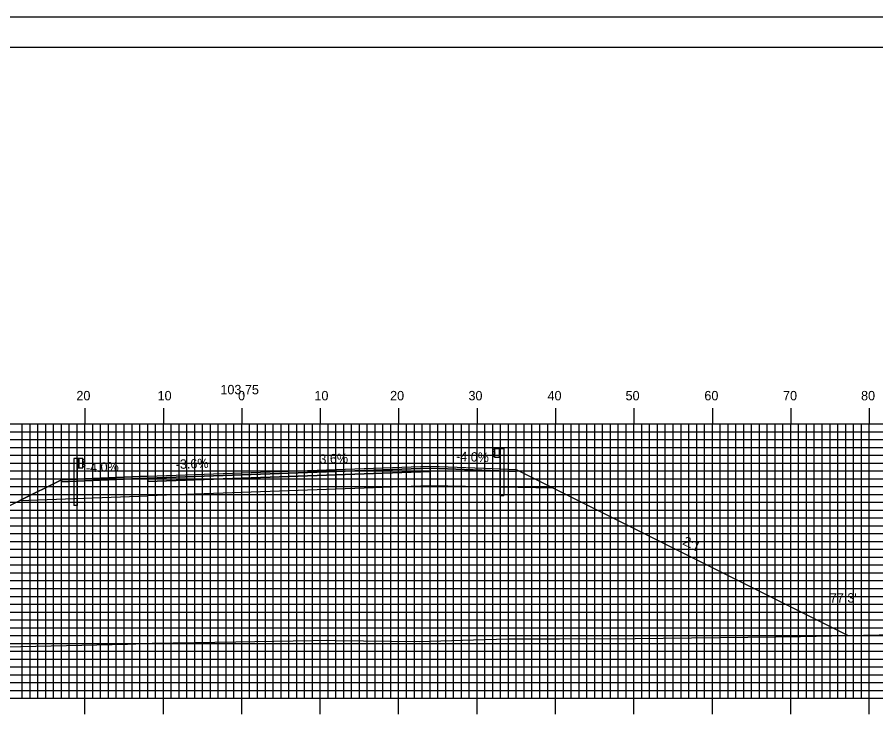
# Model space of a CAD drawing. Extents: x 1759430 to 1759773, y 442591 to 442811.
# Drawn here: x 1759567 to 1759676.5, y 442721.2 to 442810.5 of the extents above; entities that cross this region are included whole.
import ezdxf

# ---------------------------------------------------------------- set-up
doc = ezdxf.new("R2010")
doc.units = 0
for name, color, linetype in [('ANNOTATION', 7, 'Continuous'), ('BORDER', 7, 'Continuous'), ('D_Guardrail_Beam_Lt', 7, 'Continuous'), ('D_Guardrail_Beam_Rt', 7, 'Continuous'), ('D_Roadway_Centerline', 7, 'Continuous'), ('D_Roadway_Centerline_Text', 7, 'Continuous'), ('D_Roadway_Edge_Shoulder', 7, 'Continuous'), ('D_Roadway_Edge_TW', 7, 'Continuous'), ('D_Roadway_Pavement', 7, 'Continuous'), ('D_Roadway_SlopeLines', 7, 'Continuous'), ('D_Roadway_SubGrade', 7, 'Continuous'), ('D_Text_Standard', 7, 'Continuous'), ('H_V ANNOTATION', 7, 'Continuous'), ('MAJOR', 7, 'Continuous'), ('MINOR', 7, 'Continuous'), ('PLOT BOUNDARY', 7, 'Continuous'), ('S_Roadway_Centerline', 7, 'Continuous')]:
    doc.layers.add(name, color=color, linetype=linetype)

msp = doc.modelspace()

# ---------------------------------------------------------------- linework, layer by layer
at = {"layer": 'BORDER'}
msp.add_lwpolyline([(1759446.07, 442596.67), (1759766.07, 442596.67), (1759766.07, 442806.67), (1759446.07, 442806.67)], close=True, dxfattribs=at)
at = {"layer": 'D_Guardrail_Beam_Lt'}
for p, q in [((1759574.25, 442754.25), (1759574.25, 442748.25)), ((1759574.72, 442754.25), (1759574.25, 442754.25)), ((1759575.4, 442754.25), (1759574.72, 442754.25)), ((1759574.72, 442754.25), (1759574.72, 442753.08)), ((1759574.78, 442754.25), (1759574.78, 442753.08)), ((1759574.88, 442754.25), (1759574.88, 442753.08)), ((1759575.4, 442753.08), (1759575.4, 442754.25)), ((1759575.4, 442754.16), (1759575.48, 442754.15)), ((1759575.49, 442754.14), (1759575.64, 442754.04)), ((1759574.72, 442753.08), (1759575.4, 442753.08)), ((1759574.74, 442748.25), (1759574.74, 442753.08)), ((1759575.48, 442753.18), (1759575.4, 442753.16)), ((1759575.41, 442753.7), (1759575.41, 442753.63)), ((1759575.64, 442753.9), (1759575.44, 442753.76)), ((1759575.44, 442753.56), (1759575.64, 442753.43)), ((1759575.64, 442753.28), (1759575.49, 442753.18)), ((1759574.74, 442748.25), (1759574.25, 442748.25))]:
    msp.add_line(p, q, dxfattribs=at)
for centre, major_axis, start_param, end_param in [((1759575.47, 442754.11), (0.0417, 0), 0.959931, 1.376053), ((1759575.59, 442753.97), (0.0877, 0), 5.323254, 7.243116), ((1759575.49, 442753.7), (-0.0789, 0), 5.323254, 6.283185), ((1759575.49, 442753.63), (-0.0789, 0), 6.283185, 7.243116), ((1759575.47, 442753.22), (0.0417, 0), 4.907132, 5.323254), ((1759575.59, 442753.36), (0.0877, 0), 5.323254, 7.243116)]:
    msp.add_ellipse(centre, major_axis=major_axis, ratio=0.995501, start_param=start_param, end_param=end_param, dxfattribs=at)
at = {"layer": 'D_Guardrail_Beam_Rt'}
for p, q in [((1759627.86, 442755.44), (1759627.71, 442755.34)), ((1759627.71, 442755.19), (1759627.91, 442755.06)), ((1759627.95, 442755.46), (1759627.87, 442755.44)), ((1759627.95, 442755.54), (1759628.63, 442755.54)), ((1759627.95, 442754.38), (1759627.95, 442755.54)), ((1759628.47, 442755.54), (1759628.47, 442754.38)), ((1759628.57, 442755.54), (1759628.57, 442754.38)), ((1759628.63, 442755.54), (1759629.1, 442755.54)), ((1759628.63, 442755.54), (1759628.63, 442754.38)), ((1759629.1, 442755.54), (1759629.1, 442749.54)), ((1759627.91, 442754.86), (1759627.71, 442754.72)), ((1759627.71, 442754.58), (1759627.86, 442754.48)), ((1759627.87, 442754.47), (1759627.95, 442754.46)), ((1759627.94, 442754.99), (1759627.94, 442754.92)), ((1759628.63, 442754.38), (1759627.95, 442754.38)), ((1759628.61, 442749.54), (1759628.61, 442754.38)), ((1759628.61, 442749.54), (1759629.1, 442749.54))]:
    msp.add_line(p, q, dxfattribs=at)
for centre, major_axis, start_param, end_param in [((1759627.76, 442755.27), (-0.0877, 0), 5.323254, 7.243116), ((1759627.88, 442755.4), (-0.0417, 0), 4.907132, 5.323254), ((1759627.76, 442754.65), (-0.0877, 0), 5.323254, 7.243116), ((1759627.88, 442754.51), (-0.0417, 0), 0.959931, 1.376053), ((1759627.86, 442754.99), (0.0789, 0), 0, 0.959931), ((1759627.86, 442754.92), (0.0789, 0), 5.323254, 6.283185)]:
    msp.add_ellipse(centre, major_axis=major_axis, ratio=0.995501, start_param=start_param, end_param=end_param, dxfattribs=at)
at = {"layer": 'D_Roadway_Centerline'}
msp.add_lwpolyline([(1759529.64, 442730.03), (1759567.38, 442748.9), (1759572.67, 442751.54), (1759575.67, 442751.66), (1759583.67, 442751.98), (1759595.67, 442752.41), (1759607.67, 442752.85), (1759619.67, 442753.28), (1759627.67, 442752.96), (1759630.67, 442752.84), (1759635.42, 442750.46), (1759672.99, 442731.68)], dxfattribs=at)
at = {"layer": 'D_Roadway_Edge_Shoulder'}
for points in [[(1759619.67, 442753.28), (1759627.67, 442752.96), (1759627.67, 442752.96), (1759630.67, 442752.84), (1759630.67, 442752.59), (1759619.67, 442753.03)], [(1759583.67, 442751.98), (1759575.67, 442751.66), (1759575.67, 442751.66), (1759572.67, 442751.54), (1759572.67, 442751.29), (1759583.67, 442751.73)]]:
    msp.add_lwpolyline(points, close=True, dxfattribs=at)
at = {"layer": 'D_Roadway_Edge_TW'}
for points in [[(1759607.67, 442752.85), (1759619.67, 442753.28), (1759619.67, 442753.03), (1759607.67, 442752.6)], [(1759583.67, 442751.73), (1759583.67, 442751.98), (1759595.67, 442752.41), (1759607.67, 442752.85), (1759607.67, 442752.6), (1759595.67, 442752.16)]]:
    msp.add_lwpolyline(points, close=True, dxfattribs=at)
at = {"layer": 'D_Roadway_Pavement'}
for points in [[(1759607.67, 442752.6), (1759619.67, 442753.03), (1759619.67, 442752.61), (1759607.67, 442752.18)], [(1759583.67, 442751.32), (1759583.67, 442751.73), (1759595.67, 442752.16), (1759607.67, 442752.6), (1759607.67, 442752.18), (1759595.67, 442751.75)]]:
    msp.add_lwpolyline(points, close=True, dxfattribs=at)
for points in [[(1759619.67, 442753.03), (1759619.67, 442752.61)], [(1759619.67, 442753.03), (1759619.67, 442752.61)], [(1759583.67, 442751.73), (1759583.67, 442751.32)]]:
    msp.add_lwpolyline(points, dxfattribs=at)
at = {"layer": 'D_Roadway_SlopeLines'}
for points in [[(1759630.67, 442752.84), (1759672.99, 442731.68)], [(1759572.67, 442751.54), (1759529.64, 442730.03)]]:
    msp.add_lwpolyline(points, dxfattribs=at)
at = {"layer": 'D_Roadway_SubGrade'}
for points in [[(1759619.67, 442752.61), (1759619.67, 442753.03), (1759630.67, 442752.59), (1759630.67, 442752.84), (1759635.42, 442750.46), (1759619.67, 442750.78)], [(1759583.67, 442749.48), (1759583.67, 442751.32), (1759595.67, 442751.75), (1759607.67, 442752.18), (1759607.67, 442750.35), (1759595.67, 442749.91)], [(1759607.67, 442752.18), (1759619.67, 442752.61), (1759619.67, 442750.78), (1759607.67, 442750.35)], [(1759583.67, 442751.32), (1759583.67, 442751.73), (1759572.67, 442751.29), (1759572.67, 442751.54), (1759567.38, 442748.9), (1759583.67, 442749.48)]]:
    msp.add_lwpolyline(points, close=True, dxfattribs=at)
at = {"layer": 'MAJOR'}
for p, q in [((1759575.67, 442760.67), (1759575.67, 442758.67)), ((1759585.67, 442760.67), (1759585.67, 442758.67)), ((1759595.67, 442760.67), (1759595.67, 442758.67)), ((1759605.67, 442760.67), (1759605.67, 442758.67)), ((1759615.67, 442760.67), (1759615.67, 442758.67)), ((1759625.67, 442760.67), (1759625.67, 442758.67)), ((1759635.67, 442760.67), (1759635.67, 442758.67)), ((1759645.67, 442760.67), (1759645.67, 442758.67)), ((1759655.67, 442760.67), (1759655.67, 442758.67)), ((1759665.67, 442760.67), (1759665.67, 442758.67)), ((1759675.67, 442760.67), (1759675.67, 442758.67)), ((1759455.67, 442758.67), (1759735.67, 442758.67)), ((1759455.67, 442758.67), (1759735.67, 442758.67)), ((1759575.67, 442723.67), (1759575.67, 442758.67)), ((1759585.67, 442723.67), (1759585.67, 442758.67)), ((1759595.67, 442723.67), (1759595.67, 442758.67)), ((1759605.67, 442723.67), (1759605.67, 442758.67)), ((1759615.67, 442723.67), (1759615.67, 442758.67)), ((1759625.67, 442723.67), (1759625.67, 442758.67)), ((1759635.67, 442723.67), (1759635.67, 442758.67)), ((1759645.67, 442723.67), (1759645.67, 442758.67)), ((1759655.67, 442723.67), (1759655.67, 442758.67)), ((1759665.67, 442723.67), (1759665.67, 442758.67)), ((1759675.67, 442723.67), (1759675.67, 442758.67)), ((1759455.67, 442753.67), (1759735.67, 442753.67)), ((1759455.67, 442748.67), (1759735.67, 442748.67)), ((1759455.67, 442743.67), (1759735.67, 442743.67)), ((1759455.67, 442738.67), (1759735.67, 442738.67)), ((1759455.67, 442733.67), (1759735.67, 442733.67)), ((1759455.67, 442728.67), (1759735.67, 442728.67)), ((1759455.67, 442723.67), (1759735.67, 442723.67)), ((1759455.67, 442723.67), (1759735.67, 442723.67)), ((1759575.67, 442721.66), (1759575.67, 442723.67)), ((1759585.67, 442721.66), (1759585.67, 442723.67)), ((1759595.67, 442721.66), (1759595.67, 442723.67)), ((1759605.67, 442721.66), (1759605.67, 442723.67)), ((1759615.67, 442721.66), (1759615.67, 442723.67)), ((1759625.67, 442721.66), (1759625.67, 442723.67)), ((1759635.67, 442721.66), (1759635.67, 442723.67)), ((1759645.67, 442721.66), (1759645.67, 442723.67)), ((1759655.67, 442721.66), (1759655.67, 442723.67)), ((1759665.67, 442721.66), (1759665.67, 442723.67)), ((1759675.67, 442721.66), (1759675.67, 442723.67))]:
    msp.add_line(p, q, dxfattribs=at)
at = {"layer": 'MINOR'}
for p, q in [((1759567.67, 442723.67), (1759567.67, 442758.67)), ((1759568.67, 442723.67), (1759568.67, 442758.67)), ((1759569.67, 442723.67), (1759569.67, 442758.67)), ((1759570.67, 442723.67), (1759570.67, 442758.67)), ((1759571.67, 442723.67), (1759571.67, 442758.67)), ((1759572.67, 442723.67), (1759572.67, 442758.67)), ((1759573.67, 442723.67), (1759573.67, 442758.67)), ((1759574.67, 442723.67), (1759574.67, 442758.67)), ((1759576.67, 442723.67), (1759576.67, 442758.67)), ((1759577.67, 442723.67), (1759577.67, 442758.67)), ((1759578.67, 442723.67), (1759578.67, 442758.67)), ((1759579.67, 442723.67), (1759579.67, 442758.67)), ((1759580.67, 442723.67), (1759580.67, 442758.67)), ((1759581.67, 442723.67), (1759581.67, 442758.67)), ((1759582.67, 442723.67), (1759582.67, 442758.67)), ((1759583.67, 442723.67), (1759583.67, 442758.67)), ((1759584.67, 442723.67), (1759584.67, 442758.67)), ((1759586.67, 442723.67), (1759586.67, 442758.67)), ((1759587.67, 442723.67), (1759587.67, 442758.67)), ((1759588.67, 442723.67), (1759588.67, 442758.67)), ((1759589.67, 442723.67), (1759589.67, 442758.67)), ((1759590.67, 442723.67), (1759590.67, 442758.67)), ((1759591.67, 442723.67), (1759591.67, 442758.67)), ((1759592.67, 442723.67), (1759592.67, 442758.67)), ((1759593.67, 442723.67), (1759593.67, 442758.67)), ((1759594.67, 442723.67), (1759594.67, 442758.67)), ((1759596.67, 442723.67), (1759596.67, 442758.67)), ((1759597.67, 442723.67), (1759597.67, 442758.67)), ((1759598.67, 442723.67), (1759598.67, 442758.67)), ((1759599.67, 442723.67), (1759599.67, 442758.67)), ((1759600.67, 442723.67), (1759600.67, 442758.67)), ((1759601.67, 442723.67), (1759601.67, 442758.67)), ((1759602.67, 442723.67), (1759602.67, 442758.67)), ((1759603.67, 442723.67), (1759603.67, 442758.67)), ((1759604.67, 442723.67), (1759604.67, 442758.67)), ((1759606.67, 442723.67), (1759606.67, 442758.67)), ((1759607.67, 442723.67), (1759607.67, 442758.67)), ((1759608.67, 442723.67), (1759608.67, 442758.67)), ((1759609.67, 442723.67), (1759609.67, 442758.67)), ((1759610.67, 442723.67), (1759610.67, 442758.67)), ((1759611.67, 442723.67), (1759611.67, 442758.67)), ((1759612.67, 442723.67), (1759612.67, 442758.67)), ((1759613.67, 442723.67), (1759613.67, 442758.67)), ((1759614.67, 442723.67), (1759614.67, 442758.67)), ((1759616.67, 442723.67), (1759616.67, 442758.67)), ((1759617.67, 442723.67), (1759617.67, 442758.67)), ((1759618.67, 442723.67), (1759618.67, 442758.67)), ((1759619.67, 442723.67), (1759619.67, 442758.67)), ((1759620.67, 442723.67), (1759620.67, 442758.67)), ((1759621.67, 442723.67), (1759621.67, 442758.67)), ((1759622.67, 442723.67), (1759622.67, 442758.67)), ((1759623.67, 442723.67), (1759623.67, 442758.67)), ((1759624.67, 442723.67), (1759624.67, 442758.67)), ((1759626.67, 442723.67), (1759626.67, 442758.67)), ((1759627.67, 442723.67), (1759627.67, 442758.67)), ((1759628.67, 442723.67), (1759628.67, 442758.67)), ((1759629.67, 442723.67), (1759629.67, 442758.67)), ((1759630.67, 442723.67), (1759630.67, 442758.67)), ((1759631.67, 442723.67), (1759631.67, 442758.67)), ((1759632.67, 442723.67), (1759632.67, 442758.67)), ((1759633.67, 442723.67), (1759633.67, 442758.67)), ((1759634.67, 442723.67), (1759634.67, 442758.67)), ((1759636.67, 442723.67), (1759636.67, 442758.67)), ((1759637.67, 442723.67), (1759637.67, 442758.67)), ((1759638.67, 442723.67), (1759638.67, 442758.67)), ((1759639.67, 442723.67), (1759639.67, 442758.67)), ((1759640.67, 442723.67), (1759640.67, 442758.67)), ((1759641.67, 442723.67), (1759641.67, 442758.67)), ((1759642.67, 442723.67), (1759642.67, 442758.67)), ((1759643.67, 442723.67), (1759643.67, 442758.67)), ((1759644.67, 442723.67), (1759644.67, 442758.67)), ((1759646.67, 442723.67), (1759646.67, 442758.67)), ((1759647.67, 442723.67), (1759647.67, 442758.67)), ((1759648.67, 442723.67), (1759648.67, 442758.67)), ((1759649.67, 442723.67), (1759649.67, 442758.67)), ((1759650.67, 442723.67), (1759650.67, 442758.67)), ((1759651.67, 442723.67), (1759651.67, 442758.67)), ((1759652.67, 442723.67), (1759652.67, 442758.67)), ((1759653.67, 442723.67), (1759653.67, 442758.67)), ((1759654.67, 442723.67), (1759654.67, 442758.67)), ((1759656.67, 442723.67), (1759656.67, 442758.67)), ((1759657.67, 442723.67), (1759657.67, 442758.67)), ((1759658.67, 442723.67), (1759658.67, 442758.67)), ((1759659.67, 442723.67), (1759659.67, 442758.67)), ((1759660.67, 442723.67), (1759660.67, 442758.67)), ((1759661.67, 442723.67), (1759661.67, 442758.67)), ((1759662.67, 442723.67), (1759662.67, 442758.67)), ((1759663.67, 442723.67), (1759663.67, 442758.67)), ((1759664.67, 442723.67), (1759664.67, 442758.67)), ((1759666.67, 442723.67), (1759666.67, 442758.67)), ((1759667.67, 442723.67), (1759667.67, 442758.67)), ((1759668.67, 442723.67), (1759668.67, 442758.67)), ((1759669.67, 442723.67), (1759669.67, 442758.67)), ((1759670.67, 442723.67), (1759670.67, 442758.67)), ((1759671.67, 442723.67), (1759671.67, 442758.67)), ((1759672.67, 442723.67), (1759672.67, 442758.67)), ((1759673.67, 442723.67), (1759673.67, 442758.67)), ((1759674.67, 442723.67), (1759674.67, 442758.67)), ((1759455.67, 442757.67), (1759735.67, 442757.67)), ((1759455.67, 442756.67), (1759735.67, 442756.67)), ((1759455.67, 442755.67), (1759735.67, 442755.67)), ((1759455.67, 442754.67), (1759735.67, 442754.67)), ((1759455.67, 442752.67), (1759735.67, 442752.67)), ((1759455.67, 442751.67), (1759735.67, 442751.67)), ((1759455.67, 442750.67), (1759735.67, 442750.67)), ((1759455.67, 442749.67), (1759735.67, 442749.67)), ((1759455.67, 442747.67), (1759735.67, 442747.67)), ((1759455.67, 442746.67), (1759735.67, 442746.67)), ((1759455.67, 442745.67), (1759735.67, 442745.67)), ((1759455.67, 442744.67), (1759735.67, 442744.67)), ((1759455.67, 442742.67), (1759735.67, 442742.67)), ((1759455.67, 442741.67), (1759735.67, 442741.67)), ((1759455.67, 442740.67), (1759735.67, 442740.67)), ((1759455.67, 442739.67), (1759735.67, 442739.67)), ((1759455.67, 442737.67), (1759735.67, 442737.67)), ((1759455.67, 442736.67), (1759735.67, 442736.67)), ((1759455.67, 442735.67), (1759735.67, 442735.67)), ((1759455.67, 442734.67), (1759735.67, 442734.67)), ((1759455.67, 442732.67), (1759735.67, 442732.67)), ((1759455.67, 442731.67), (1759735.67, 442731.67)), ((1759455.67, 442730.67), (1759735.67, 442730.67)), ((1759455.67, 442729.67), (1759735.67, 442729.67)), ((1759455.67, 442727.67), (1759735.67, 442727.67)), ((1759455.67, 442726.67), (1759735.67, 442726.67)), ((1759455.67, 442725.67), (1759735.67, 442725.67)), ((1759455.67, 442724.67), (1759735.67, 442724.67))]:
    msp.add_line(p, q, dxfattribs=at)
at = {"layer": 'PLOT BOUNDARY'}
msp.add_lwpolyline([(1759429.89, 442590.55), (1759769.89, 442590.55), (1759769.89, 442810.55), (1759429.89, 442810.55)], close=True, dxfattribs=at)
at = {"layer": 'S_Roadway_Centerline'}
msp.add_lwpolyline([(1759563.55, 442730.2), (1759581.08, 442730.58), (1759584.25, 442730.7), (1759594.89, 442730.87), (1759604.66, 442731.04), (1759606.49, 442731.06), (1759607.67, 442731.05), (1759618.28, 442730.91), (1759625.21, 442731.13), (1759629.63, 442731.24), (1759636.18, 442731.23), (1759645.83, 442731.29), (1759663.75, 442731.52), (1759666.9, 442731.56), (1759674.93, 442731.72), (1759686.82, 442731.98), (1759691.02, 442731.9), (1759706.99, 442731.98), (1759717.95, 442731.9), (1759726.46, 442731.74), (1759735.39, 442731.84), (1759735.67, 442731.84)], dxfattribs=at)

# ---------------------------------------------------------------- texts
at = {"layer": 'ANNOTATION'}
for s, rotation, p in [('-4.0%', 357.7094, (1759622.97, 442753.95)), ('-3.6%', 2.0618, (1759587.26, 442752.91)), ('3.6%', 2.0618, (1759605.58, 442753.57)), ('-4.0%', 2.2906, (1759575.81, 442752.47)), ('2:1', 333.4349, (1759651.77, 442743.33))]:
    msp.add_text(s, height=1.2, rotation=rotation, dxfattribs=at).set_placement(p)
at = {"layer": 'D_Roadway_Centerline'}
for s in ['C', 'L']:
    msp.add_text(s, height=0.0146, dxfattribs=at).set_placement((1759595.67, 442752.41))
at = {"layer": 'D_Roadway_Centerline_Text'}
msp.add_text('103.75', height=1.2, dxfattribs=at).set_placement((1759592.94, 442762.44))
at = {"layer": 'D_Text_Standard'}
msp.add_text("77.3'", height=1.2, dxfattribs=at).set_placement((1759670.65, 442735.87))
at = {"layer": 'H_V ANNOTATION'}
for s, p in [('20', (1759574.58, 442761.67)), ('10', (1759584.93, 442761.67)), ('0', (1759595.19, 442761.67)), ('10', (1759604.93, 442761.67)), ('20', (1759614.58, 442761.67)), ('30', (1759624.57, 442761.67)), ('40', (1759634.65, 442761.67)), ('50', (1759644.6, 442761.67)), ('60', (1759654.65, 442761.67)), ('70', (1759664.68, 442761.67)), ('80', (1759674.63, 442761.67))]:
    msp.add_text(s, height=1.2, dxfattribs=at).set_placement(p)

doc.saveas('drawing.dxf')
